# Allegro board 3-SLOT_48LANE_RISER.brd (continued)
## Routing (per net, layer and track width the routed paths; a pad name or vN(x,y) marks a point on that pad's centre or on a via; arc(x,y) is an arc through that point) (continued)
PE_SLOT2_TX_C_DN<15>: length 180.3
  BOTTOM w0.135: C78.1 218.06,44.8 218.06,45.23 218.03,45.26 217.91,45.41 217.69,45.68 217.69,45.68 212.87,46.53 212.44,46.23 212.31,45.49 212.09,45.34 211.83,45.39 211.68,45.6 211.81,46.35 211.51,46.77 211.08,47.04 127.05,61.86 v6(118.85,60.41) 96.81,56.53 90.15,51.86 89.93,51.9 89.49,51.6 89.45,51.37 89.01,51.06 88.78,51.1 88.34,50.79 88.3,50.57 87.86,50.26 87.63,50.3 87.19,49.99 87.15,49.76 86.47,49.29 83.87,48.83 79.52,49.59 78.46,50.34 77.56,50.5 71.38,50.5 69.85,52.02 64.82,52.02 61.3,55.54 61.3,55.77 60.92,56.15 60.69,56.15 60.31,56.53 60.31,56.76 59.93,57.14 59.7,57.14 59.32,57.52 59.32,57.75 58.94,58.13 58.71,58.13 57.84,59 57.84,59.73 57.99,59.88 57.99,60.42 57.84,60.57 57.84,61.11 57.99,61.26 57.99,61.8 57.84,61.95 57.84,65.79 57.94,65.89 57.94,66.65 U1.V1
PE_SLOT2_TX_C_DP<0>: length 219.2
  BOTTOM w0.135: U1.B11 71.1,74.52 71.26,74.36 73.88,74.36 74.32,74.8 78.21,74.8 78.44,74.57 82.8,74.57 125.88,82.17 v6(131.01,81.27) 132.5,81 260.82,58.26 274.09,48.96 278.32,48.21 280.94,46.38 281.23,46.05 281.62,45.5 281.62,44.82 C27.1
PE_SLOT2_TX_C_DP<1>: length 217.5
  BOTTOM w0.135: U1.B10 71.1,73.72 71.26,73.56 76.66,73.56 76.94,73.29 83.89,73.29 v6(124.51,80.45) 125.35,80.6 259.72,56.74 265.51,52.69 265.56,52.43 265.12,51.8 265.2,51.3 265.63,51 266.15,51.09 266.58,51.71 266.85,51.75 267.06,51.6 267.11,51.34 266.67,50.71 266.76,50.24 267.18,49.94 267.69,50.03 268.1,50.61 268.4,50.67 268.62,50.51 268.66,50.25 268.14,49.51 268.23,49 268.66,48.7 269.17,48.79 269.69,49.53 269.95,49.58 272.87,47.53 273.43,46.74 273.65,45.5 273.65,44.82 C28.1
PE_SLOT2_TX_C_DP<2>: length 206.7
  BOTTOM w0.135: U1.B8 71.1,72.12 71.26,71.96 73.23,71.96 73.63,72.36 76.15,72.36 76.58,71.93 84.09,71.93 125.33,79.2 127.29,78.86 v6(128.82,78.59) 190.03,67.74 254.74,56.27 260.92,51.94 261.81,51.32 261.92,51.24 262.45,50.87 269.08,46.23 269.32,45.98 269.65,45.5 269.65,44.82 C29.1
PE_SLOT2_TX_C_DP<3>: length 204.8
  BOTTOM w0.135: C30.1 265.65,44.82 265.65,45.5 265.61,45.74 265.42,46.01 263.39,47.43 263.13,47.39 262.9,47.07 262.39,46.98 261.97,47.28 261.88,47.79 262.1,48.11 262.05,48.37 261.83,48.52 261.57,48.47 261.35,48.16 261.09,48.11 260.84,48.07 260.41,48.37 260.32,48.9 260.54,49.22 260.5,49.46 254.22,53.86 251.82,55.53 126.44,77.79 v6(124.74,77.49) 123.43,77.26 85.45,70.56 75.86,70.56 75.26,71.16 73.14,71.16 73.14,71.16 71.26,71.16 71.1,71.32 U1.B7
PE_SLOT2_TX_C_DP<4>: length 196.4
  BOTTOM w0.135: U1.B5 71.1,69.72 71.26,69.56 72.51,69.56 72.91,69.96 74.37,69.96 75.16,69.16 84.51,69.16 v6(120.53,75.52) 121.86,75.75 126.43,76.56 245.98,55.35 259.28,46.03 259.56,45.64 259.56,45.63 259.65,45.5 259.65,44.82 C55.1
PE_SLOT2_TX_C_DP<5>: length 194
  BOTTOM w0.135: U1.B4 71.1,68.92 71.26,68.76 72.92,68.76 72.93,68.76 73.84,68.76 74.8,67.79 83.85,67.79 v6(123.67,74.81) 125.09,75.06 126.53,75.32 243.27,54.6 246.02,52.67 249.12,50.51 249.73,50.61 249.81,50.72 250.17,50.78 250.48,50.57 250.54,50.21 250.32,49.88 250.42,49.28 250.93,48.92 251.56,49.03 251.78,49.34 252.14,49.41 254.36,47.85 254.82,47.19 255.65,45.19 255.65,44.82 C56.1
PE_SLOT2_TX_C_DP<6>: length 187.9
  BOTTOM w0.135: U1.B2 71.1,67.32 71.26,67.16 72.6,67.16 72.98,66.78 74.09,66.78 74.48,66.4 83.17,66.4 v6(120.34,72.95) 121.76,73.2 126.26,73.99 241.28,53.71 241.52,53.54 250.76,47.07 251.58,45.91 251.58,45.9 251.65,45.5 251.65,44.82 C57.1
PE_SLOT2_TX_C_DP<7>: length 186.4
  BOTTOM w0.135: U1.B1 71.1,66.52 71.1,66.19 71.53,65.76 73.74,65.76 74.35,65.15 84.29,65.15 v6(117.27,70.97) 118.83,71.24 126.89,72.66 240.53,52.5 242.68,50.99 242.72,50.73 242.61,50.57 242.7,50.06 243.12,49.76 243.63,49.85 243.75,50.01 244.01,50.06 244.23,49.91 244.28,49.64 244.16,49.48 244.25,48.97 244.68,48.67 245.19,48.76 245.3,48.93 245.57,48.97 247.01,47.96 247.65,46.98 247.65,44.82 C58.1
PE_SLOT2_TX_C_DP<8>: length 188.5
  BOTTOM w0.135: C59.1 245.62,44.82 245.62,45.39 245.18,46.03 237.03,51.75 126.77,71.19 123.57,70.63 v6(122.1,70.37) 84.73,63.78 74.48,63.78 73.41,64.85 72.54,64.85 71.98,64.29 67.57,64.29 65.66,66.2 65.66,67.17 U1.H2
PE_SLOT2_TX_C_DP<9>: length 187.4
  BOTTOM w0.135: U1.J2 64.86,67.17 64.86,65.73 65.23,65.35 65.23,64.87 66.38,63.72 66.38,63.72 66.63,63.47 72.85,63.47 73.99,62.33 84.66,62.33 v6(117.5,68.12) 119.07,68.4 126.88,69.78 164.27,63.18 236.6,50.42 238.33,49.21 238.37,48.95 238.19,48.69 238.28,48.18 238.7,47.88 239.21,47.97 239.4,48.23 239.66,48.28 240.98,47.35 241.41,46.74 241.63,45.5 241.63,44.82 C60.1
PE_SLOT2_TX_C_DP<10>: length 185
  BOTTOM w0.135: C61.1 237.67,44.82 237.67,45.58 237.56,46.21 232.43,49.79 211.51,53.48 211.51,53.48 210.36,53.68 210.36,53.68 199.37,55.62 199.37,55.62 127.18,68.34 123.97,67.78 v6(122.17,67.46) 85.02,60.91 65.61,60.91 64.75,61.77 64.75,63.96 63.26,65.45 63.26,67.17 U1.L2
PE_SLOT2_TX_C_DP<11>: length 183.5
  BOTTOM w0.135: C62.1 233.71,44.82 233.71,45.5 233.66,45.77 232.6,47.28 230.69,48.62 229.33,48.86 229.15,48.74 228.62,48.83 228.5,49.01 227.97,49.1 227.79,48.98 227.26,49.07 227.14,49.25 222.62,50.05 221.45,50.26 211.28,52.06 211.28,52.06 200.27,54.01 200.27,54.01 199.26,54.19 199.13,54.22 126.86,67.04 119.39,65.72 v6(117.85,65.45) 80.86,58.93 65.48,58.93 63.4,61.01 63.4,63.6 62.46,64.55 62.46,67.17 U1.M2
PE_SLOT2_TX_C_DP<12>: length 181.2
  BOTTOM w0.135: C63.1 229.67,44.82 229.67,46.16 227.44,47.72 126.46,65.53 123.35,64.98 v6(121.87,64.72) 81.11,57.53 64.9,57.53 61.78,60.65 61.78,63.7 60.86,64.62 60.86,67.17 U1.P2
PE_SLOT2_TX_C_DP<13>: length 180.9
  BOTTOM w0.135: U1.R2 60.06,67.17 60.06,63.82 60.28,63.6 60.28,60.22 65.89,54.61 70.31,54.61 71.99,52.93 76.99,52.93 77.7,53.07 82.4,56.36 v6(118.1,62.65) 119.88,62.97 126.73,64.18 222.39,47.31 225.29,45.88 225.69,45.51 225.73,45.41 225.73,44.82 C64.1
PE_SLOT2_TX_C_DP<14>: length 180.3
  BOTTOM w0.135: U1.U2 58.46,67.17 58.46,65.57 58.78,65.25 58.78,62.53 58.96,62.36 58.96,59.59 65.56,52.98 70.23,52.98 71.69,51.53 79.5,51.53 81.14,50.38 83.31,50 85.61,50.38 95.51,57.3 111.25,60.08 v6(120.93,61.79) 123.14,62.18 126.99,62.86 220.26,46.41 221.27,45.69 221.76,45.21 221.76,44.85 C65.1
PE_SLOT2_TX_C_DP<15>: length 180.2
  BOTTOM w0.135: U1.V2 57.63,67.15 57.63,66.01 57.53,65.91 57.53,58.88 64.7,51.71 69.73,51.71 71.25,50.19 77.53,50.19 78.34,50.05 79.4,49.31 83.87,48.52 86.59,49 96.93,56.24 v6(117.39,59.85) 118.9,60.11 127.05,61.55 210.96,46.75 211.33,46.49 211.48,46.27 211.35,45.53 211.65,45.11 212.16,45.02 212.59,45.31 212.72,46.06 212.94,46.21 217.53,45.4 217.64,45.26 217.68,45.21 217.76,45.12 217.76,44.85 C66.1
PE_SLOT2_TX_DN<0>: length 7.4
  BOTTOM w0.135: J2.B15 280.59,38.51 arc(280.65,38.55) 280.72,38.57 281.17,38.57 arc(281.76,38.81) 282,39.4 282,43.39 C31.2
PE_SLOT2_TX_DN<1>: length 7.5
  BOTTOM w0.135: C32.2 273.98,43.34 273.98,42.44 274.16,42.26 274.16,41.82 273.98,41.65 273.98,41.21 274.16,41.03 274.16,40.59 273.98,40.41 273.98,39.34 arc(274.16,38.92) 274.58,38.74 275.01,38.74 arc(275.33,38.96) 275.25,39.33 J2.B20
PE_SLOT2_TX_DN<2>: length 7.5
  BOTTOM w0.135: J2.B24 271.25,39.33 arc(271.33,38.96) 271.01,38.74 270.58,38.74 arc(270.16,38.92) 269.98,39.34 269.98,40.41 270.16,40.59 270.16,41.03 269.98,41.21 269.98,41.65 270.16,41.82 270.16,42.26 269.98,42.44 269.98,43.34 C33.2
PE_SLOT2_TX_DN<3>: length 7.5
  BOTTOM w0.135: C34.2 265.98,43.34 265.98,42.44 266.16,42.26 266.16,41.82 265.98,41.65 265.98,41.21 266.16,41.03 266.16,40.59 265.98,40.41 265.98,39.34 arc(266.16,38.92) 266.58,38.74 267.01,38.74 arc(267.33,38.96) 267.25,39.33 J2.B28
PE_SLOT2_TX_DN<4>: length 7.5
  BOTTOM w0.135: C67.2 259.98,43.34 259.98,42.44 260.16,42.26 260.16,41.82 259.98,41.65 259.98,41.21 260.16,41.03 260.16,40.59 259.98,40.41 259.98,39.34 arc(260.16,38.92) 260.58,38.74 261.01,38.74 arc(261.33,38.96) 261.25,39.33 J2.B34
PE_SLOT2_TX_DN<5>: length 7.5
  BOTTOM w0.135: C68.2 255.98,43.34 255.98,42.44 256.16,42.26 256.16,41.82 255.98,41.65 255.98,41.21 256.16,41.03 256.16,40.59 255.98,40.41 255.98,39.34 arc(256.16,38.92) 256.58,38.74 257.01,38.74 arc(257.33,38.96) 257.25,39.33 J2.B38
PE_SLOT2_TX_DN<6>: length 7.5
  BOTTOM w0.135: C69.2 251.98,43.34 251.98,42.44 252.16,42.26 252.16,41.82 251.98,41.65 251.98,41.21 252.16,41.03 252.16,40.59 251.98,40.41 251.98,39.34 arc(252.16,38.92) 252.58,38.74 253.01,38.74 arc(253.33,38.96) 253.25,39.33 J2.B42
PE_SLOT2_TX_DN<7>: length 7.5
  BOTTOM w0.135: C70.2 247.98,43.34 247.98,42.44 248.16,42.26 248.16,41.82 247.98,41.65 247.98,41.21 248.16,41.03 248.16,40.59 247.98,40.41 247.98,39.34 arc(248.16,38.92) 248.58,38.74 249.01,38.74 arc(249.33,38.96) 249.25,39.33 J2.B46
PE_SLOT2_TX_DN<8>: length 7.4
  BOTTOM w0.135: J2.B51 244.59,38.51 arc(244.65,38.55) 244.72,38.57 245.17,38.57 arc(245.76,38.81) 246,39.4 246,43.39 C71.2
PE_SLOT2_TX_DN<9>: length 7.4
  BOTTOM w0.135: J2.B55 240.59,38.51 arc(240.65,38.55) 240.72,38.57 241.17,38.57 arc(241.76,38.81) 242,39.4 242,43.38 C72.2
PE_SLOT2_TX_DN<10>: length 7.4
  BOTTOM w0.135: J2.B59 236.59,38.51 arc(236.65,38.55) 236.72,38.57 237.17,38.57 arc(237.76,38.81) 238,39.4 238,43.34 C73.2
PE_SLOT2_TX_DN<11>: length 7.4
  BOTTOM w0.135: J2.B63 232.59,38.51 arc(232.65,38.55) 232.72,38.57 233.17,38.57 arc(233.76,38.81) 234,39.4 234,43.3 C74.2
PE_SLOT2_TX_DN<12>: length 7.4
  BOTTOM w0.135: J2.B67 228.59,38.51 arc(228.65,38.55) 228.72,38.57 229.17,38.57 arc(229.76,38.81) 230,39.4 230,43.34 C75.2
PE_SLOT2_TX_DN<13>: length 7.4
  BOTTOM w0.135: C76.2 226,43.28 226,39.4 arc(225.76,38.81) 225.17,38.57 224.72,38.57 arc(224.65,38.55) 224.59,38.51 J2.B71
PE_SLOT2_TX_DN<14>: length 7.4
  BOTTOM w0.135: C77.2 222,43.28 222,39.4 arc(221.76,38.81) 221.17,38.57 220.72,38.57 arc(220.65,38.55) 220.59,38.51 J2.B75
PE_SLOT2_TX_DN<15>: length 7.4
  BOTTOM w0.135: C78.2 218,43.28 218,39.4 arc(217.76,38.81) 217.17,38.57 216.72,38.57 arc(216.65,38.55) 216.59,38.51 J2.B79
PE_SLOT2_TX_DP<0>: length 7.4
  BOTTOM w0.135: C27.2 281.7,43.24 281.7,42.34 281.54,42.19 281.54,41.78 281.7,41.63 281.7,41.23 281.54,41.07 281.54,40.67 281.7,40.52 281.7,39.4 arc(281.54,39.03) 281.17,38.87 280.58,38.87 arc(280.34,39.03) 280.39,39.32 J2.B14
PE_SLOT2_TX_DP<1>: length 7.5
  BOTTOM w0.135: C28.2 273.68,43.29 273.68,39.34 arc(273.94,38.71) 274.58,38.44 275.15,38.44 arc(275.63,38.24) 275.83,37.76 J2.B19
PE_SLOT2_TX_DP<2>: length 7.5
  BOTTOM w0.135: C29.2 269.68,43.29 269.68,39.34 arc(269.94,38.71) 270.58,38.44 271.15,38.44 arc(271.63,38.24) 271.83,37.76 J2.B23
PE_SLOT2_TX_DP<3>: length 7.5
  BOTTOM w0.135: C30.2 265.68,43.29 265.68,39.34 arc(265.94,38.71) 266.58,38.44 267.15,38.44 arc(267.63,38.24) 267.83,37.76 J2.B27
PE_SLOT2_TX_DP<4>: length 7.5
  BOTTOM w0.135: J2.B33 261.83,37.76 arc(261.63,38.24) 261.15,38.44 260.58,38.44 arc(259.94,38.71) 259.68,39.34 259.68,43.29 C55.2
PE_SLOT2_TX_DP<5>: length 7.5
  BOTTOM w0.135: C56.2 255.68,43.29 255.68,39.34 arc(255.94,38.71) 256.58,38.44 257.15,38.44 arc(257.63,38.24) 257.83,37.76 J2.B37
PE_SLOT2_TX_DP<6>: length 7.5
  BOTTOM w0.135: C57.2 251.68,43.29 251.68,39.34 arc(251.94,38.71) 252.58,38.44 253.15,38.44 arc(253.63,38.24) 253.83,37.76 J2.B41
PE_SLOT2_TX_DP<7>: length 7.5
  BOTTOM w0.135: J2.B45 249.83,37.76 arc(249.63,38.24) 249.15,38.44 248.58,38.44 arc(247.94,38.71) 247.68,39.34 247.68,43.29 C58.2
PE_SLOT2_TX_DP<8>: length 7.4
  BOTTOM w0.135: C59.2 245.7,43.24 245.7,42.34 245.54,42.19 245.54,41.78 245.7,41.63 245.7,41.23 245.54,41.07 245.54,40.67 245.7,40.52 245.7,39.4 arc(245.54,39.03) 245.17,38.87 244.58,38.87 arc(244.34,39.03) 244.39,39.32 J2.B50
PE_SLOT2_TX_DP<9>: length 7.4
  BOTTOM w0.135: C60.2 241.7,43.25 241.7,42.34 241.54,42.19 241.54,41.78 241.7,41.63 241.7,41.23 241.54,41.07 241.54,40.67 241.7,40.52 241.7,39.4 arc(241.54,39.03) 241.17,38.87 240.56,38.87 arc(240.33,39.03) 240.38,39.31 J2.B54
PE_SLOT2_TX_DP<10>: length 7.4
  BOTTOM w0.135: J2.B58 236.36,39.28 arc(236.31,39.02) 236.53,38.87 237.17,38.87 arc(237.54,39.03) 237.69,39.4 237.69,40.52 237.54,40.67 237.54,41.07 237.69,41.23 237.69,41.63 237.54,41.78 237.54,42.19 237.69,42.34 237.69,43.29 C61.2
PE_SLOT2_TX_DP<11>: length 7.4
  BOTTOM w0.135: C62.2 233.69,43.33 233.69,42.34 233.54,42.19 233.54,41.78 233.69,41.63 233.69,41.23 233.54,41.07 233.54,40.67 233.69,40.52 233.69,39.4 arc(233.54,39.03) 233.17,38.87 232.5,38.87 arc(232.29,39.01) 232.34,39.26 J2.B62
PE_SLOT2_TX_DP<12>: length 7.4
  BOTTOM w0.135: J2.B66 228.36,39.29 arc(228.31,39.02) 228.53,38.87 229.17,38.87 arc(229.54,39.03) 229.69,39.4 229.69,40.52 229.54,40.67 229.54,41.07 229.69,41.23 229.69,41.63 229.54,41.78 229.54,42.19 229.69,42.34 229.69,43.29 C63.2
PE_SLOT2_TX_DP<13>: length 7.4
  BOTTOM w0.135: C64.2 225.7,43.35 225.7,42.34 225.54,42.19 225.54,41.78 225.7,41.63 225.7,41.23 225.54,41.07 225.54,40.67 225.7,40.52 225.7,39.4 arc(225.54,39.03) 225.17,38.87 224.5,38.87 arc(224.29,39.01) 224.34,39.26 J2.B70
PE_SLOT2_TX_DP<14>: length 7.4
  BOTTOM w0.135: J2.B74 220.34,39.26 arc(220.29,39.01) 220.5,38.87 221.17,38.87 arc(221.54,39.03) 221.7,39.4 221.7,40.52 221.54,40.67 221.54,41.07 221.7,41.23 221.7,41.63 221.54,41.78 221.54,42.19 221.7,42.34 221.7,43.35 C65.2
PE_SLOT2_TX_DP<15>: length 7.4
  BOTTOM w0.135: C66.2 217.7,43.35 217.7,42.34 217.54,42.19 217.54,41.78 217.7,41.63 217.7,41.23 217.54,41.07 217.54,40.67 217.7,40.52 217.7,39.4 arc(217.54,39.03) 217.17,38.87 216.5,38.87 arc(216.29,39.01) 216.34,39.26 J2.B78
PE_SLOT3_PRES_N: length 175.2
  TOP w0.114: J3.B81 213.22,78.39 211.2,80.42 205.46,80.42 200.97,75.92 190.4,75.92 189.31,74.83 159.3,74.83 133.23,100.89 v2(114.25,100.89) ; R45.2 59.01,97.92 64.48,103.39 105.66,103.39 v2(107.37,101.68)
  IN2 w0.147: v2(107.37,101.68) 108.15,100.89 v2(114.25,100.89)
PE_SLOT3_RX_DN<0>: length 249.2
  IN2 w0.089: 57.53,85.19 57.53,85.16 57.48,85.12 57.47,84.99 57.47,82.55 v3(57.65,82.37)
  IN2 w0.145: 57.53,85.19 57.58,85.69 57.73,85.82 57.79,86.43 57.66,86.59 57.71,87.16 57.84,87.27 57.9,87.93 57.79,88.06 57.86,88.81 58.13,89.2 58.33,89.23 58.66,89.71 58.62,89.91 58.96,90.38 59.16,90.42 59.49,90.89 59.45,91.09 59.79,91.57 59.99,91.6 60.32,92.08 60.28,92.28 60.51,92.6 63.87,94.95 64.47,95.06 64.61,94.96 65.26,95.07 65.36,95.21 65.93,95.32 66.07,95.21 66.71,95.33 66.81,95.47 68.75,95.81 73.01,98.8 73.59,98.9 73.74,98.8 74.38,98.91 74.48,99.06 75.05,99.16 75.17,99.07 75.86,99.19 75.95,99.31 83.09,100.57 86.81,99.92 86.9,99.78 87.55,99.67 87.68,99.76 88.25,99.66 88.35,99.52 88.98,99.41 89.12,99.51 89.69,99.41 89.78,99.28 90.44,99.17 90.56,99.26 91.13,99.15 91.21,99.04 91.89,98.92 92.01,99 104.53,96.79 105.39,96.94 105.51,96.86 106.16,96.98 106.25,97.09 106.82,97.2 106.93,97.11 107.59,97.23 107.67,97.35 108.24,97.45 108.36,97.36 109.02,97.48 109.1,97.6 129.58,101.21 129.7,101.12 130.39,101.24 130.48,101.37 132.66,101.76 136.67,101.05 143.25,102.21 171.41,97.24 189.42,100.42 189.52,100.34 190.23,100.47 190.31,100.57 191.05,100.71 191.15,100.63 191.86,100.76 191.93,100.86 193.18,101.08 205.8,98.86 212.11,99.97 272.89,89.25 272.89,89.25 273.67,89.12 275.82,87.75 276.15,87.27 276.13,87.15 276.53,86.58 276.65,86.56 276.98,86.08 276.96,85.94 277.34,85.39 277.49,85.37 277.72,85.03 278.07,83.07 277.67,80.85 277.67,79.94 278.7,78.92 278.7,75.32 278.55,75.16 278.42,75.1 278.19,75.17 J3.A17
  BOTTOM w0.135: U1.V20 v3(57.65,82.37)
PE_SLOT3_RX_DN<1>: length 249.3
  IN2 w0.089: 58.68,84.32 58.67,84.3 58.62,84.27 58.56,84.15 58.39,83.91 58.03,83.38 58.03,83 58.27,82.75 58.27,82.55 v3(58.45,82.37)
  IN2 w0.145: 58.68,84.32 58.73,84.45 58.85,85.12 58.77,85.59 58.87,86.15 59,86.24 59.12,86.92 59.03,87.05 59.08,87.38 59.13,87.62 59.27,87.72 59.39,88.38 59.29,88.52 59.38,89.08 59.72,89.55 59.86,89.58 60.25,90.14 60.23,90.29 61.02,91.41 62.35,92.35 62.49,92.33 63.06,92.73 63.09,92.86 64.21,93.65 65.61,93.9 65.75,93.8 66.39,93.91 66.49,94.05 67.06,94.15 67.19,94.06 67.85,94.17 67.94,94.31 68.51,94.41 68.63,94.32 69.3,94.44 69.39,94.56 69.96,94.66 70.07,94.59 70.76,94.71 70.84,94.82 71.41,94.92 71.55,94.82 72.19,94.94 72.29,95.07 75.65,95.67 76.78,95.47 77.24,95.79 77.5,97.27 77.67,97.39 78.03,97.33 78.15,97.16 77.89,95.68 78.17,95.26 78.29,95.24 78.67,95.18 79.08,95.47 79.34,96.95 79.51,97.07 79.87,97.01 79.99,96.84 79.72,95.35 80.01,94.94 83.45,94.34 87.89,95.12 87.89,95.12 97.59,96.83 104.21,95.66 132.82,100.71 133.28,100.63 133.35,100.52 134.09,100.39 134.19,100.46 134.76,100.36 134.84,100.25 135.56,100.13 135.67,100.2 136.26,100.1 143.38,101.35 171.67,96.38 193.37,100.2 205.87,98 212.25,99.13 267.55,89.38 270.36,88.88 273.05,87 273.54,86.31 273.66,85.57 273.66,85.26 273.55,85.15 273.55,84.45 273.66,84.33 273.66,83.75 273.53,83.62 273.53,82.96 273.66,82.83 273.66,82.25 273.53,82.12 273.53,81.45 273.66,81.32 273.66,79.87 272.69,78.89 272.69,75.19 272.95,74.93 273.14,74.83 273.2,74.64 J3.A22
  BOTTOM w0.135: U1.U20 v3(58.45,82.37)
PE_SLOT3_RX_DN<2>: length 235.9
  IN2 w0.089: v3(60.05,82.37) 59.87,82.55 59.87,85.48 59.91,85.53 59.91,85.55
  IN2 w0.145: 59.91,85.55 59.91,85.69 60.19,87.25 60.34,87.35 60.34,87.38 60.45,87.98 60.34,88.14 60.45,88.75 60.84,89.31 61,89.33 61.39,89.89 61.36,90.05 61.75,90.6 62.16,90.89 62.33,90.86 62.9,91.26 62.93,91.43 63.4,91.76 63.58,91.73 64.14,92.13 64.18,92.3 64.68,92.65 65.68,92.83 65.82,92.74 66.48,92.85 66.57,92.99 67.14,93.09 67.26,93.01 67.95,93.13 68.03,93.25 68.6,93.35 68.72,93.27 69.41,93.39 69.49,93.5 70.06,93.6 70.18,93.52 70.87,93.65 70.95,93.76 71.52,93.86 71.63,93.79 72.34,93.91 72.41,94.02 72.98,94.12 73.09,94.05 73.8,94.17 73.87,94.28 75.56,94.57 83.21,93.22 84.9,93.52 85.02,93.43 85.68,93.55 85.77,93.67 86.34,93.78 86.46,93.69 87.12,93.81 87.21,93.93 87.78,94.03 87.9,93.94 88.56,94.06 88.64,94.18 89.22,94.28 89.34,94.2 90,94.31 90.08,94.44 90.65,94.54 90.78,94.45 91.44,94.57 91.52,94.69 92.09,94.79 93.53,95.05 93.53,95.05 94.97,95.3 97.7,95.78 104.04,94.66 132.29,99.64 135.68,99.04 143.62,100.44 144.47,100.29 172.55,95.34 194.19,99.15 206.38,97 213,98.17 265.47,88.92 268.54,86.77 269.62,85.23 270.03,82.89 269.66,80.8 269.66,79.87 268.69,78.89 268.69,75.19 268.95,74.93 269.14,74.84 269.15,74.82 269.21,74.66 J3.A26
  BOTTOM w0.135: U1.R20 v3(60.05,82.37)
PE_SLOT3_RX_DN<3>: length 234.2
  IN2 w0.089: v3(60.85,82.37) 60.43,82.79 60.43,83.77 60.46,83.94 60.84,84.48 60.9,84.86 60.93,84.99 60.98,85.03 60.98,85.05
  IN2 w0.145: 60.98,85.05 61.07,85.52 61.19,85.61 61.3,86.26 61.22,86.39 61.32,86.96 61.45,87.05 61.51,87.38 61.57,87.68 61.47,87.82 61.59,88.49 62.65,90.01 62.97,90.23 63.16,90.2 63.66,90.55 63.7,90.74 64.86,91.56 65.83,91.73 65.96,91.64 66.61,91.75 66.7,91.88 67.27,91.98 67.4,91.89 68.05,92.01 68.14,92.14 68.71,92.24 68.84,92.15 69.5,92.26 69.58,92.39 70.16,92.49 70.28,92.4 70.94,92.52 71.03,92.65 75.64,93.46 82.98,92.16 83.69,92.04 85,92.27 85.13,92.18 85.77,92.29 85.86,92.42 86.43,92.52 86.53,92.45 87.23,92.58 87.3,92.67 87.87,92.78 87.99,92.69 88.65,92.81 88.73,92.93 89.31,93.03 89.4,92.96 90.1,93.09 90.17,93.18 91.17,93.36 94.16,92.83 94.63,92.92 94.92,93.33 94.78,94.15 94.93,94.37 95.2,94.42 95.42,94.26 95.57,93.44 95.98,93.15 96.47,93.24 96.76,93.65 96.61,94.47 96.77,94.7 97.04,94.74 97.26,94.59 97.4,93.76 97.81,93.48 101.57,94.14 103.77,93.75 104.78,93.93 106.23,94.19 106.23,94.19 107.68,94.44 107.68,94.44 108.56,94.59 108.56,94.6 131.87,98.71 135.54,98.06 143.94,99.54 144.4,99.46 172.97,94.42 194.11,98.15 206.41,95.98 213.59,97.25 260.84,88.91 261.44,88.49 261.46,88.36 262.04,87.96 262.17,87.98 262.65,87.65 262.66,87.56 263.29,87.12 263.38,87.13 264.41,86.41 265.66,84.62 265.66,83.82 265.57,83.72 265.57,82.97 265.66,82.88 265.66,82.3 265.56,82.19 265.56,81.46 265.66,81.35 265.66,79.87 264.69,78.89 264.69,75.19 264.95,74.93 265.14,74.84 265.15,74.82 265.24,74.56 264.92,73.93 J3.A30
  BOTTOM w0.135: U1.P20 v3(60.85,82.37)
PE_SLOT3_RX_DN<4>: length 222.9
  IN2 w0.145: v3(63.25,82.37) 62.99,82.11 62.79,82.11 62.57,82.32 62.57,82.82 62.64,82.89 62.64,83.68 62.57,83.75 62.57,84.33 62.66,84.42 62.66,85.17 62.57,85.26 62.57,85.84 62.67,85.94 62.67,86.67 62.57,86.77 62.57,87.29 62.6,87.46 63.53,88.78 63.89,89.04 65,89.23 65.88,89.08 66.62,89.19 68.08,90.21 68.2,90.26 71.83,90.9 71.96,90.81 72.66,90.93 72.75,91.06 73.32,91.16 73.45,91.07 74.14,91.2 74.24,91.33 74.81,91.43 74.92,91.35 75.64,91.47 75.72,91.59 76.29,91.69 76.41,91.61 77.13,91.74 77.21,91.85 77.95,91.98 83.73,90.96 91.34,92.3 94.5,91.75 95.35,91.9 95.49,91.8 96.14,91.91 96.24,92.05 96.81,92.16 96.98,92.04 97.59,92.15 97.71,92.31 98.28,92.41 98.43,92.31 99.07,92.42 99.17,92.57 101.63,93.01 103.49,92.68 131.62,97.64 134.83,97.07 144.02,98.69 144.48,98.61 172.97,93.59 194.15,97.32 206.4,95.16 213.59,96.43 257.73,88.64 258.67,87.99 259.42,86.92 259.66,85.52 259.66,79.87 258.69,78.89 258.69,75.19 258.95,74.93 259.14,74.84 259.15,74.82 259.21,74.66 J3.A36
  BOTTOM w0.124: U1.M20 v3(63.25,82.37)
PE_SLOT3_RX_DN<5>: length 222.6
  IN2 w0.089: 63.82,85.76 63.81,85.74 63.75,85.72 63.33,84.72 63.33,84.54 63.42,84.45 63.42,84.1 63.33,84.01 63.33,83.74 63.42,83.65 63.42,83.36 63.33,83.27 63.33,83.09 63.51,82.91 63.62,82.91 63.79,82.74 63.79,82.63 v3(64.05,82.37)
  IN2 w0.145: 63.82,85.76 64.15,86.23 64.46,86.45 64.6,86.42 64.98,86.69 65,86.83 65.2,86.96 65.65,87.04 65.73,86.99 66.47,87.12 66.53,87.2 67.53,87.38 68.86,88.3 69.04,88.27 69.51,88.6 69.54,88.78 69.91,89.04 70.41,89.13 70.51,89.06 71.17,89.17 71.23,89.25 71.66,89.33 72.39,89.2 72.47,89.09 73.18,88.96 73.3,89.04 73.87,88.94 73.96,88.81 74.65,88.69 74.78,88.78 76.64,88.45 77.53,88.61 77.82,89.02 77.52,90.73 77.67,90.95 77.94,91 78.16,90.85 78.46,89.13 78.88,88.85 79.37,88.93 79.66,89.35 79.44,90.56 79.56,90.73 79.92,90.79 80.09,90.67 80.3,89.46 80.71,89.17 82.54,89.49 82.63,89.43 83.43,89.57 83.49,89.66 84.07,89.76 84.17,89.69 84.95,89.83 85.02,89.93 85.59,90.03 85.7,89.95 86.47,90.09 86.55,90.2 87.12,90.3 87.23,90.22 88,90.36 88.07,90.47 88.64,90.57 88.75,90.5 89.53,90.64 89.6,90.74 92.14,91.19 94.65,90.74 95.85,90.96 95.97,90.88 96.75,91.01 96.83,91.13 97.4,91.23 97.51,91.15 98.29,91.29 98.37,91.4 98.94,91.5 99.04,91.43 99.84,91.57 99.91,91.67 101.55,91.96 103.42,91.63 131.95,96.66 134.8,96.16 144.06,97.79 144.06,97.79 144.98,97.63 172.97,92.7 194.19,96.44 206.23,94.31 213.26,95.55 223.55,93.74 233.83,91.93 233.83,91.93 254.4,88.3 255.03,87.86 255.47,87.23 255.66,86.11 255.66,79.87 254.69,78.89 254.69,75.19 254.95,74.93 255.14,74.84 255.15,74.82 255.21,74.66 J3.A40
  BOTTOM w0.135: U1.L20 v3(64.05,82.37)
PE_SLOT3_RX_DN<6>: length 209.3
  IN2 w0.089: v3(65.65,82.37) 65.48,82.54 65.48,82.61 65.35,82.74 65.35,82.84 65.07,83.12 64.96,83.12 64.81,83.27 64.81,83.79 64.89,83.86 64.89,84.36 64.81,84.44 64.81,84.74 64.86,84.78 64.86,84.8
  IN2 w0.145: 64.86,84.8 64.86,85.01 64.93,85.38 65.3,85.91 65.83,86.29 67.7,86.62 67.81,86.54 68.49,86.66 68.56,86.77 69.13,86.87 69.24,86.79 69.91,86.91 69.99,87.02 71.52,87.29 73.46,86.95 74.13,87.06 74.24,86.98 74.94,87.1 75.04,87.25 75.56,87.35 75.72,87.23 76.4,87.35 76.51,87.51 77.03,87.6 77.22,87.47 77.84,87.58 77.98,87.77 78.49,87.86 78.67,87.74 79.33,87.86 79.45,88.03 91.84,90.22 94.68,89.72 95.83,89.92 95.94,89.85 96.66,89.97 96.73,90.08 97.3,90.18 97.43,90.09 98.11,90.21 98.2,90.34 98.77,90.44 98.9,90.35 99.58,90.47 99.67,90.59 101.58,90.93 103.66,90.57 104.51,90.72 104.65,90.62 105.35,90.74 105.45,90.88 106.02,90.98 106.16,90.89 106.86,91.01 106.96,91.15 131.82,95.53 134.49,95.06 135.25,95.2 135.37,95.11 136.06,95.23 136.14,95.35 136.71,95.45 136.83,95.37 137.53,95.49 137.61,95.61 144.54,96.83 172.91,91.83 194.28,95.6 194.36,95.58 206.22,93.49 213.26,94.74 249.67,88.32 250.93,87.44 251.42,86.73 251.66,85.34 251.66,79.87 250.69,78.89 250.69,75.19 250.95,74.93 251.14,74.84 251.15,74.82 251.21,74.66 J3.A44
  BOTTOM w0.135: U1.J20 v3(65.65,82.37)
PE_SLOT3_RX_DN<7>: length 209.2
  IN2 w0.089: v3(66.45,82.37) 66.27,82.55 66.27,82.97 66.34,83.03 66.34,83.57 66.27,83.63 66.27,83.95 66.28,84.08 66.33,84.12 66.33,84.14
  IN2 w0.145: J3.A48 247.21,74.66 247.15,74.82 247.14,74.84 246.95,74.93 246.69,75.19 246.69,78.96 247.68,79.95 247.68,80.75 246.78,85.85 245.5,87.68 244.44,88.42 213.26,93.92 206.22,92.68 194.38,94.76 172.48,90.9 145.55,95.65 144.54,95.83 133.91,93.95 131.54,94.37 103.91,89.5 101.87,89.86 94.89,88.63 92,89.14 91.32,89.02 91.16,88.8 91.45,87.17 91.2,86.82 90.62,86.71 90.26,86.96 89.97,88.59 89.75,88.74 89.48,88.69 89.33,88.47 89.61,86.88 89.36,86.52 88.77,86.42 88.42,86.67 88.33,87.17 88.21,87.25 88.14,87.67 88.22,87.78 88.13,88.26 87.92,88.41 87.52,88.34 87.45,88.24 86.93,88.15 86.83,88.22 86.3,88.13 86.21,88 85.63,87.9 85.5,87.99 85.01,87.9 84.93,87.78 84.34,87.67 84.22,87.76 83.73,87.67 83.64,87.55 83.05,87.44 82.93,87.53 82.44,87.44 82.36,87.32 81.77,87.22 81.64,87.3 81.16,87.22 81.07,87.09 80.48,86.99 80.36,87.08 79.87,86.99 79.78,86.87 79.2,86.76 79.07,86.85 78.48,86.75 78.42,86.66 77.65,86.52 77.56,86.58 76.97,86.48 76.91,86.39 76.15,86.25 76.05,86.32 75.42,86.21 75.34,86.09 74.38,85.92 74.26,86 73.67,85.9 73.5,85.87 73.49,85.87 72.6,86.02 72.46,85.92 71.86,86.03 71.76,86.17 70.9,86.32 69.94,86.16 69.82,85.98 69.33,85.89 69.15,86.02 68.66,85.93 68.54,85.76 68.04,85.67 67.87,85.79 67.43,85.71 66.75,85.24 66.38,84.71 66.33,84.14
  BOTTOM w0.135: U1.H20 v3(66.45,82.37)
PE_SLOT3_RX_DN<8>: length 190.8
  IN2 w0.145: v3(69.65,84.77) 69.65,84.98 69.8,85.13 72.5,85.13 73.72,84.91 74.37,85.03 74.45,84.97 74.5,84.93 75,85.02 75.09,85.15 75.51,85.23 75.64,85.14 76.14,85.22 76.23,85.36 76.65,85.43 76.78,85.34 77.28,85.42 77.38,85.56 77.79,85.63 77.92,85.54 78.42,85.63 78.52,85.76 78.93,85.83 79.07,85.74 79.56,85.83 79.66,85.96 80.07,86.03 80.21,85.94 80.71,86.03 80.8,86.16 81.22,86.23 81.36,86.13 81.84,86.21 81.94,86.36 82.67,86.49 88.76,85.41 92.14,86.01 93.27,86.8 94.33,86.98 94.46,86.89 95.09,87 95.19,87.14 95.76,87.24 95.89,87.14 96.52,87.26 96.62,87.39 97.19,87.49 97.32,87.4 97.96,87.51 98.05,87.64 98.62,87.74 98.75,87.65 99.39,87.76 99.48,87.89 100.05,87.99 100.18,87.9 100.82,88.01 100.91,88.15 101.48,88.25 101.61,88.15 102.25,88.27 102.34,88.4 131.56,93.55 134.25,93.07 144.66,94.91 145.28,94.8 145.28,94.8 172.66,89.98 194.77,93.88 206.22,91.86 213.26,93.1 232.6,89.69 232.73,89.49 233.18,89.42 233.37,89.55 233.81,89.47 233.95,89.28 234.4,89.2 234.59,89.34 236.04,89.08 236.46,88.47 240.17,87.82 241.7,85.64 241.7,79.88 242.67,78.9 242.67,75.29 242.54,75.16 242.4,75.08 242.2,75.15 J3.A53
  BOTTOM w0.135: U1.D23 v3(69.65,84.77)
PE_SLOT3_RX_DN<9>: length 189.3
  IN2 w0.089: 72.89,84.31 72.87,84.31 72.82,84.35 72.29,84.35 72.2,84.26 71.84,84.26 71.75,84.35 71.4,84.35 71.31,84.26 70.95,84.26 70.86,84.35 70.04,84.35 v3(69.65,83.97)
  IN2 w0.145: 72.89,84.31 73.04,84.31 74.45,84.06 74.46,84.06 74.6,84.06 74.6,84.06 74.63,84.06 75.48,84.21 75.64,84.1 76.31,84.22 76.42,84.38 76.93,84.47 77.05,84.39 77.79,84.52 77.87,84.63 78.38,84.72 78.47,84.66 79.26,84.8 79.32,84.89 79.83,84.98 79.94,84.9 80.7,85.04 80.77,85.14 81.29,85.24 81.38,85.17 82.16,85.3 82.23,85.4 83.1,85.55 88.85,84.54 92.88,85.25 93.76,85.87 96.56,86.36 96.79,86.21 97.05,84.74 97.46,84.45 97.95,84.54 98.24,84.95 97.98,86.42 98.13,86.64 99.54,86.89 99.69,86.79 100.33,86.9 100.43,87.05 101,87.15 101.14,87.04 101.79,87.16 101.89,87.3 102.46,87.4 102.58,87.32 103.26,87.44 103.34,87.56 103.91,87.66 104.04,87.57 104.71,87.69 104.8,87.82 105.37,87.92 105.5,87.83 106.17,87.95 106.26,88.07 107.51,88.29 107.64,88.2 108.3,88.32 108.39,88.45 108.96,88.55 109.09,88.46 109.74,88.57 109.83,88.7 131.59,92.54 133.85,92.14 144.69,94.05 145.54,93.9 172.65,89.12 194.87,93.04 206.22,91.04 212.7,92.18 227.71,89.53 227.84,89.34 228.29,89.26 228.48,89.4 228.93,89.32 229.06,89.13 229.5,89.05 229.7,89.18 230.26,89.08 231.32,88.34 232.04,87.84 235.93,87.16 236.69,86.63 237.22,85.86 237.69,83.19 237.69,79.89 238.69,78.9 238.69,75.3 238.54,75.16 238.4,75.08 238.2,75.15 J3.A57
  BOTTOM w0.135: U1.D22 v3(69.65,83.97)
PE_SLOT3_RX_DN<10>: length 182.3
  IN2 w0.089: 72.25,83.35 72.23,83.34 72.18,83.38 72.05,83.36 71.57,83.27 70.99,82.87 70.35,82.75 70.04,82.75 v3(69.65,82.37)
  IN2 w0.145: 72.25,83.35 73.06,83.49 74.45,83.24 75.41,83.07 75.99,83.18 76.13,83.08 76.81,83.2 76.9,83.34 77.47,83.44 77.59,83.35 78.3,83.48 78.38,83.6 78.95,83.7 79.08,83.61 79.77,83.73 79.86,83.86 80.43,83.96 80.56,83.87 81.25,84 81.34,84.12 81.91,84.22 82.04,84.13 82.73,84.26 82.82,84.38 83.28,84.46 83.29,84.46 83.75,84.54 88.71,83.67 89.32,83.78 89.43,83.7 90.11,83.83 90.19,83.93 90.76,84.03 90.87,83.95 91.54,84.06 91.62,84.18 92.79,84.39 93.71,84.23 93.79,84.11 94.57,83.97 94.69,84.06 97.29,83.6 99.17,83.93 102.82,86.49 104.33,86.75 104.5,86.64 105.19,86.76 105.31,86.92 105.88,87.03 106,86.94 106.76,87.07 106.85,87.2 107.42,87.3 107.55,87.21 108.3,87.34 108.39,87.47 131.66,91.57 133.68,91.22 144.89,93.19 145.88,93.02 145.94,92.92 146.66,92.8 146.75,92.87 147.32,92.77 147.4,92.66 148.1,92.54 148.2,92.61 148.77,92.51 148.84,92.41 149.55,92.28 149.65,92.36 172.64,88.3 194.59,92.17 206.13,90.14 212.42,91.25 222.16,89.53 222.24,89.41 222.9,89.29 223.02,89.38 223.59,89.28 223.66,89.18 224.35,89.06 224.45,89.13 225.02,89.03 225.1,88.92 225.77,88.8 225.88,88.87 227.02,88.67 228.84,87.4 232.12,86.82 232.97,86.23 233.17,85.94 233.44,84.41 233.37,83.98 233.73,81.92 233.73,79.89 234.69,78.94 234.69,75.3 234.54,75.16 234.4,75.08 234.2,75.15 J3.A61
  BOTTOM w0.135: U1.D20 v3(69.65,82.37)
PE_SLOT3_RX_DN<11>: length 181.7
  IN2 w0.089: v3(69.65,81.57) 70.04,81.95 70.82,81.95 70.86,81.91 70.9,81.86 71.26,81.86 71.3,81.91 71.35,81.95 71.7,81.95 71.75,81.91 71.79,81.86 72.15,81.86 72.19,81.91 72.24,81.95 73.26,81.95 73.28,81.93
  IN2 w0.145: J3.A65 230.2,75.15 230.4,75.08 230.54,75.16 230.68,75.3 230.68,78.88 229.69,79.88 229.69,81.19 230.02,81.53 231.79,81.53 231.93,81.67 231.93,82.04 231.79,82.18 230.02,82.18 229.67,82.54 229.67,84.77 228.7,86.15 226.84,87.45 225.18,87.74 225.05,87.65 224.3,87.78 224.21,87.91 223.64,88.01 223.5,87.91 222.77,88.04 222.67,88.18 222.1,88.28 221.94,88.17 221.24,88.3 221.13,88.45 220.56,88.55 220.41,88.45 219.7,88.57 219.59,88.73 219.02,88.83 218.84,88.7 218.18,88.81 218.05,89 211.63,90.13 206.35,89.2 202.14,89.94 201.98,89.82 201.35,89.93 201.24,90.1 200.67,90.2 200.52,90.1 199.86,90.21 199.76,90.36 199.19,90.46 199.07,90.38 198.37,90.5 198.28,90.62 197.71,90.72 197.57,90.62 196.9,90.74 196.8,90.88 195.12,91.18 172.11,87.12 144.83,91.93 133.57,89.95 131.5,90.31 108.19,86.2 108.1,86.07 107.39,85.94 107.26,86.04 106.73,85.94 106.64,85.81 105.94,85.68 105.8,85.78 105.28,85.69 105.19,85.56 104.47,85.43 104.34,85.52 103.1,85.3 100.14,83.23 96.91,82.67 92.82,83.39 92.61,83.34 88.03,82.51 83.56,83.3 83.01,83.2 82.9,83.04 82.18,82.92 82.02,83.03 81.5,82.94 81.38,82.76 80.69,82.64 80.52,82.76 75.62,81.9 74.52,82.09 74.51,82.09 74.24,82.09 73.29,81.93 73.28,81.93
  BOTTOM w0.135: U1.D19 v3(69.65,81.57)
PE_SLOT3_RX_DN<12>: length 173.6
  IN2 w0.089: 74.45,80.49 74.43,80.49 74.38,80.53 73.41,80.53 72.89,80.9 72.26,80.9 71.34,80.26 70.87,80.17 69.86,80.17 v3(69.65,79.97)
  IN2 w0.145: J3.A69 226.2,75.15 226.4,75.08 226.54,75.16 226.68,75.3 226.68,78.88 225.68,79.88 225.68,81.07 225.96,82.63 225.49,85.25 224.75,86.31 224.75,86.31 224.01,86.83 221.34,87.3 221.2,87.2 220.56,87.31 220.47,87.45 219.9,87.55 219.75,87.45 219.13,87.56 219.03,87.7 218.46,87.81 218.33,87.71 217.68,87.83 217.59,87.96 217.02,88.06 216.87,87.96 216.25,88.07 216.15,88.21 215.58,88.31 215.44,88.22 214.8,88.33 214.71,88.47 211.17,89.09 205.94,88.17 204.56,88.41 204.45,88.33 203.72,88.46 203.64,88.57 203.07,88.67 202.95,88.59 202.23,88.72 202.15,88.84 201.58,88.94 201.45,88.85 200.75,88.97 200.65,89.1 200.08,89.2 199.97,89.12 199.24,89.25 199.16,89.36 198.59,89.46 198.48,89.38 197.75,89.51 197.67,89.63 197.1,89.73 196.95,89.62 196.28,89.74 196.18,89.89 194.43,90.2 171.67,86.18 144.65,90.95 103.14,83.63 101.04,82.16 97.09,81.46 92.57,82.26 91.05,81.99 90.95,81.84 90.28,81.72 90.13,81.83 89.55,81.73 89.47,81.6 88.75,81.47 88.63,81.56 88.01,81.46 84.41,82.09 80.45,81.39 80.37,81.29 79.69,81.16 79.58,81.24 79.01,81.14 78.92,81.02 78.26,80.9 78.14,80.99 77.56,80.88 77.47,80.75 76.83,80.63 76.69,80.73 75.3,80.49 74.45,80.49
  BOTTOM w0.135: U1.D17 v3(69.65,79.97)
PE_SLOT3_RX_DN<13>: length 173.7
  IN2 w0.089: 73.02,79.51 72.99,79.51 72.95,79.55 70.04,79.55 v3(69.65,79.17)
  IN2 w0.145: 73.02,79.51 74.19,79.51 75.39,79.3 76.35,79.47 76.47,79.38 77.14,79.5 77.22,79.62 77.79,79.72 77.91,79.64 78.59,79.76 78.67,79.88 79.24,79.98 79.34,79.91 80.05,80.03 80.12,80.13 80.69,80.23 80.82,80.14 81.47,80.25 81.57,80.39 84.79,80.95 88.08,80.37 88.79,80.5 88.93,80.4 89.63,80.52 89.73,80.66 90.3,80.76 90.44,80.66 91.13,80.79 91.23,80.93 92.82,81.21 97.02,80.47 101.22,81.21 103.4,82.73 107.02,83.37 107.24,83.22 107.35,82.59 107.71,82.34 108.29,82.44 108.54,82.8 108.43,83.43 108.59,83.65 108.85,83.7 109.07,83.54 109.17,82.98 109.53,82.73 110.12,82.83 110.37,83.19 110.27,83.75 110.42,83.97 110.69,84.02 110.91,83.87 111.01,83.3 111.37,83.05 111.95,83.15 112.2,83.51 112.1,84.08 112.26,84.3 144.76,90.03 172.02,85.22 194.13,89.12 195.97,88.8 196.04,88.69 196.58,88.6 196.68,88.67 197.11,88.6 197.18,88.49 197.72,88.4 197.82,88.47 198.25,88.4 198.34,88.27 198.83,88.18 198.96,88.27 199.39,88.2 199.47,88.08 199.99,87.99 200.11,88.07 205.36,87.14 210.52,88.05 211.58,87.87 211.69,87.71 212.27,87.61 212.42,87.72 212.86,87.64 212.97,87.5 213.56,87.39 213.71,87.49 214.15,87.41 214.27,87.24 214.81,87.14 214.98,87.26 214.99,87.27 215.44,87.19 215.55,87.02 216.11,86.92 216.27,87.03 216.28,87.04 216.72,86.96 216.85,86.78 217.38,86.68 217.55,86.8 217.56,86.81 218.01,86.73 218.12,86.58 218.69,86.48 218.84,86.58 218.85,86.58 220.06,86.37 220.83,85.83 221.16,85.36 221.69,82.37 221.69,79.87 222.68,78.88 222.68,75.3 222.54,75.16 222.4,75.08 222.2,75.15 J3.A73
  BOTTOM w0.135: U1.D16 v3(69.65,79.17)
PE_SLOT3_RX_DN<14>: length 161.4
  IN2 w0.089: 72.9,78.45 72.89,78.45 72.88,78.47 72.85,78.51 72.36,78.59 71.76,78.45 70.92,77.85 70.48,77.77 69.86,77.77 v3(69.65,77.57)
  IN2 w0.145: 72.9,78.45 74.45,78.29 75.32,78.2 76.31,78.38 76.47,78.27 76.99,78.36 77.09,78.51 77.45,78.58 77.58,78.49 78.15,78.59 78.23,78.71 78.6,78.78 78.73,78.68 79.28,78.78 79.37,78.91 79.74,78.98 79.9,78.87 80.4,78.95 80.52,79.12 80.88,79.18 81.02,79.08 81.56,79.18 81.66,79.32 82.02,79.38 82.13,79.3 82.72,79.41 82.8,79.52 84.52,79.82 88.03,79.2 92.3,79.96 96.94,79.14 148.87,88.3 172.36,84.15 175.13,84.64 175.24,84.57 175.8,84.67 175.87,84.77 176.27,84.84 176.34,84.79 176.96,84.9 177.02,84.98 177.41,85.05 177.49,84.99 178.1,85.1 178.16,85.18 193.96,87.96 200.54,86.8 200.63,86.69 201.16,86.59 201.28,86.67 201.69,86.6 201.78,86.46 202.28,86.37 202.42,86.47 202.83,86.4 202.94,86.24 203.4,86.16 203.56,86.27 203.97,86.2 204.07,86.05 204.55,85.96 204.7,86.07 205.11,86 205.21,85.85 205.7,85.77 205.84,85.87 206.25,85.8 206.35,85.66 206.85,85.57 206.98,85.67 207.39,85.6 207.5,85.44 207.97,85.36 208.13,85.47 212.8,84.64 214.91,83.17 216,82.72 217.18,81.89 217.56,81.34 217.71,80.51 217.71,79.86 218.68,78.88 218.68,75.3 218.54,75.16 218.4,75.08 218.2,75.15 J3.A77
  BOTTOM w0.135: U1.D14 v3(69.65,77.57)
PE_SLOT3_RX_DN<15>: length 160.6
  IN2 w0.089: v3(69.65,76.77) 70.04,77.15 71.12,77.15 71.16,77.1 71.21,77.06 71.61,77.06 71.65,77.1 71.7,77.15 72.1,77.15 72.15,77.1 72.19,77.06 72.59,77.06 72.64,77.1 72.68,77.15 73.4,77.15 73.44,77.11 73.46,77.11
  IN2 w0.145: J3.A81 214.2,75.15 214.4,75.08 214.54,75.16 214.68,75.3 214.68,78.88 213.67,79.89 213.67,81.36 213.54,82.06 212.79,83.13 211.98,83.7 208.63,84.29 208.54,84.23 207.97,84.33 207.91,84.42 207.49,84.49 207.38,84.41 206.84,84.51 206.76,84.62 206.35,84.69 206.25,84.62 205.7,84.72 205.62,84.82 205.21,84.89 205.1,84.82 204.56,84.91 204.48,85.02 204.07,85.1 203.95,85.01 203.42,85.11 203.34,85.22 202.93,85.3 202.81,85.22 202.28,85.31 202.2,85.42 201.79,85.5 201.65,85.4 201.16,85.48 201.06,85.63 194.73,86.74 175.23,83.3 175.23,83.3 172.27,82.78 148.69,86.94 104.16,79.09 104.01,78.87 104.1,78.35 103.85,77.99 103.26,77.89 102.9,78.14 102.81,78.66 102.59,78.81 102.32,78.77 102.17,78.54 102.27,78 102.02,77.64 101.43,77.54 101.07,77.79 100.97,78.33 100.46,78.7 99.15,78.46 99.07,78.35 98.4,78.23 98.28,78.31 97.71,78.21 97.63,78.09 96.97,77.98 96.85,78.06 96.22,77.95 92.1,78.67 91.19,78.51 91.11,78.39 90.43,78.27 90.31,78.36 89.74,78.26 89.65,78.12 88.99,78.01 88.86,78.1 87.89,77.93 84.38,78.55 82.07,78.14 81.99,78.03 81.46,77.93 81.35,78.01 80.93,77.94 80.85,77.83 80.31,77.74 80.21,77.81 79.79,77.74 79.7,77.62 79.18,77.53 79.07,77.61 78.65,77.54 78.56,77.42 78.05,77.33 77.93,77.41 77.5,77.34 77.42,77.22 76.91,77.13 76.79,77.21 75.5,76.98 73.91,77.11 73.91,77.11 73.46,77.11
  BOTTOM w0.135: U1.D13 v3(69.65,76.77)
PE_SLOT3_RX_DP<0>: length 249.3
  IN2 w0.089: v3(57.65,81.57) 57.28,81.94 57.28,85.01 57.29,85.14 57.25,85.19 57.25,85.21
  IN2 w0.145: 57.25,85.21 57.39,86.7 57.54,88.46 57.55,88.46 57.59,88.91 60.31,92.8 63.76,95.22 68.64,96.08 72.9,99.06 83.09,100.86 104.53,97.08 132.66,102.04 136.67,101.33 143.25,102.49 171.41,97.53 193.18,101.37 205.8,99.14 212.11,100.25 272.94,89.53 272.94,89.53 273.77,89.38 276.02,87.95 277.98,85.14 278.35,83.07 277.95,80.82 277.95,80.06 278.98,79.03 278.98,75.2 278.71,74.93 278.52,74.84 278.46,74.64 J3.A16
  BOTTOM w0.135: v3(57.65,81.57) 58.05,81.17 U1.V19
PE_SLOT3_RX_DP<1>: length 249.4
  IN2 w0.089: v3(58.45,81.57) 58.08,81.94 58.08,82.68 57.84,82.92 57.84,83.44 58.24,84.02 58.38,84.22 58.44,84.35 58.41,84.4 58.42,84.42
  IN2 w0.145: 58.42,84.42 58.46,84.53 58.57,85.12 58.48,85.59 58.8,87.38 59.12,89.19 60.82,91.62 64.1,93.91 75.65,95.95 76.72,95.76 76.99,95.95 77.25,97.44 77.61,97.69 78.19,97.58 78.44,97.22 78.18,95.74 78.34,95.52 78.6,95.47 78.82,95.63 79.09,97.11 79.44,97.36 80.03,97.26 80.28,96.9 80.02,95.42 80.17,95.2 83.44,94.62 87.84,95.4 97.58,97.11 104.21,95.95 132.82,100.99 136.26,100.38 139.77,101 143.38,101.64 171.67,96.66 193.37,100.49 205.87,98.28 212.25,99.41 270.47,89.15 273.25,87.2 273.8,86.42 273.94,85.6 273.94,79.76 272.97,78.78 272.97,75.31 273.12,75.16 273.26,75.08 273.46,75.15 J3.A21
  BOTTOM w0.124: U1.U19 v3(58.45,81.57)
PE_SLOT3_RX_DP<2>: length 236
  IN2 w0.089: v3(60.05,81.57) 59.68,81.94 59.68,85.48 59.63,85.53 59.63,85.55
  IN2 w0.145: 59.63,85.55 59.63,85.72 60.19,88.86 61.55,90.81 64.57,92.92 75.55,94.86 83.2,93.51 97.69,96.06 104.04,94.94 132.29,99.93 135.68,99.33 143.62,100.73 144.47,100.58 172.55,95.62 194.19,99.44 206.38,97.29 213,98.45 265.58,89.18 268.74,86.97 269.89,85.34 270.32,82.89 269.94,80.77 269.94,79.76 268.97,78.78 268.97,75.31 269.12,75.16 269.26,75.08 269.46,75.15 J3.A25
  BOTTOM w0.135: v3(60.05,81.57) 60.45,81.17 U1.R19
PE_SLOT3_RX_DP<3>: length 234.3
  IN2 w0.089: v3(60.85,81.57) 60.48,81.94 60.48,82.47 60.24,82.71 60.24,83.79 60.28,84.02 60.66,84.56 60.72,84.89 60.74,85.03 60.7,85.08 60.71,85.1
  IN2 w0.145: 60.71,85.1 61.33,88.6 62.45,90.21 64.76,91.82 75.63,93.74 83.68,92.32 91.17,93.64 94.16,93.12 94.47,93.17 94.63,93.39 94.48,94.22 94.77,94.63 95.26,94.71 95.68,94.43 95.82,93.6 96.04,93.45 96.31,93.5 96.46,93.72 96.32,94.54 96.61,94.95 97.1,95.04 97.51,94.75 97.66,93.93 97.88,93.77 101.57,94.42 103.77,94.04 104.73,94.21 104.73,94.21 108.51,94.87 108.51,94.87 131.86,98.99 135.54,98.34 143.94,99.82 144.4,99.74 172.97,94.7 194.11,98.43 206.41,96.26 213.59,97.53 260.95,89.18 264.61,86.61 265.94,84.71 265.94,79.76 264.97,78.78 264.97,75.31 265.12,75.16 265.26,75.08 265.46,75.15 J3.A29
  BOTTOM w0.135: U1.P19 61.25,81.17 v3(60.85,81.57)
PE_SLOT3_RX_DP<4>: length 223
  IN2 w0.145: J3.A35 259.46,75.15 259.26,75.08 259.12,75.16 258.97,75.31 258.97,78.78 259.94,79.76 259.94,85.54 259.68,87.03 258.87,88.19 257.84,88.91 213.59,96.71 206.4,95.45 194.15,97.61 172.97,93.87 144.48,98.9 144.02,98.98 134.83,97.36 131.62,97.92 103.49,92.96 101.63,93.29 94.5,92.03 91.34,92.59 83.73,91.25 77.95,92.27 68.1,90.53 67.97,90.48 66.55,89.48 65.88,89.36 65,89.52 63.78,89.3 63.33,88.99 62.33,87.57 62.3,87.38 62.29,87.31 62.29,82.21 62.67,81.83 62.99,81.83 v3(63.25,81.57)
  BOTTOM w0.124: U1.M19 v3(63.25,81.57)
PE_SLOT3_RX_DP<5>: length 222.7
  IN2 w0.089: v3(64.05,81.57) 63.68,81.94 63.68,82.47 63.14,83.01 63.14,84.75 63.57,85.79 63.54,85.85 63.56,85.87
  IN2 w0.145: 63.56,85.87 63.95,86.43 65.09,87.23 65.92,87.38 66.11,87.41 66.29,87.44 67.37,87.6 69.8,89.3 71.61,89.62 76.64,88.74 77.37,88.87 77.53,89.09 77.22,90.8 77.51,91.21 78.01,91.3 78.42,91.01 78.72,89.3 78.94,89.14 79.21,89.19 79.36,89.41 79.15,90.63 79.4,90.98 79.99,91.09 80.34,90.84 80.56,89.62 80.78,89.47 92.14,91.47 94.65,91.03 101.54,92.24 103.42,91.91 131.95,96.95 134.8,96.44 144.01,98.07 144.02,98.07 144.06,98.08 144.98,97.92 172.97,92.98 194.19,96.72 206.23,94.6 213.26,95.84 254.51,88.57 255.23,88.06 255.73,87.34 255.94,86.13 255.94,79.76 254.97,78.78 254.97,75.31 255.12,75.16 255.26,75.08 255.46,75.15 J3.A39
  BOTTOM w0.135: U1.L19 v3(64.05,81.57)
PE_SLOT3_RX_DP<6>: length 209.4
  IN2 w0.089: v3(65.65,81.57) 65.28,81.94 65.28,82.54 64.62,83.19 64.62,84.74 64.58,84.78 64.58,84.8
  IN2 w0.145: 64.58,84.8 64.58,85.03 64.66,85.49 65.1,86.11 65.72,86.55 69.94,87.3 69.94,87.3 70.39,87.38 71.52,87.57 72.62,87.38 73.37,87.24 74.12,87.38 85.59,89.4 91.84,90.5 94.68,90 101.58,91.22 103.66,90.85 131.82,95.82 134.49,95.35 144.54,97.12 145.51,96.95 172.91,92.12 194.28,95.88 194.36,95.87 206.22,93.78 213.26,95.02 249.78,88.58 251.13,87.64 251.69,86.84 251.94,85.37 251.94,79.76 250.97,78.78 250.97,75.31 251.12,75.16 251.26,75.08 251.46,75.15 J3.A43
  BOTTOM w0.135: U1.J19 v3(65.65,81.57)
PE_SLOT3_RX_DP<7>: length 209.3
  IN2 w0.089: v3(66.45,81.57) 66.45,81.84 66.08,82.21 66.08,83.96 66.09,84.1 66.05,84.14 66.05,84.17
  IN2 w0.145: 66.05,84.17 66.05,84.17 66.11,84.81 66.55,85.44 67.32,85.98 70.9,86.61 73.49,86.15 74.45,86.32 87.99,88.71 88.39,88.42 88.67,86.83 88.84,86.71 89.2,86.78 89.31,86.94 89.03,88.54 89.32,88.95 89.82,89.04 90.23,88.75 90.51,87.13 90.68,87.01 91.04,87.07 91.16,87.24 90.87,88.86 91.16,89.27 92,89.42 94.89,88.91 101.87,90.14 103.91,89.78 131.54,94.65 133.91,94.24 144.54,96.11 145.55,95.93 172.48,91.18 194.38,95.05 206.22,92.96 213.26,94.2 244.55,88.68 245.7,87.88 247.04,85.96 247.96,80.77 247.96,79.83 246.97,78.84 246.97,75.31 247.12,75.16 247.26,75.08 247.46,75.15 J3.A47
  BOTTOM w0.135: U1.H19 v3(66.45,81.57)
PE_SLOT3_RX_DP<8>: length 190.9
  IN2 w0.145: J3.A52 242.46,74.64 242.52,74.84 242.7,74.93 242.95,75.18 242.95,79.02 241.98,79.99 241.98,85.72 240.33,88.08 236.63,88.73 236.2,89.34 234.64,89.61 213.26,93.38 206.22,92.14 194.77,94.16 172.66,90.26 145.36,95.07 145.33,95.08 145.3,95.08 144.66,95.2 134.25,93.36 131.56,93.83 102.29,88.67 93.16,87.06 92.03,86.27 88.76,85.7 82.66,86.77 74.45,85.32 73.72,85.2 72.52,85.41 69.68,85.41 69.04,84.77 v3(68.85,84.77)
  BOTTOM w0.135: U1.E23 v3(68.85,84.77)
PE_SLOT3_RX_DP<9>: length 189.4
  IN2 w0.089: 72.89,84.59 72.87,84.59 72.82,84.54 69.96,84.54 69.78,84.37 69.42,84.37 v3(68.85,83.97)
  IN2 w0.145: J3.A56 238.45,74.65 238.51,74.83 238.52,74.84 238.7,74.93 238.96,75.19 238.96,79.02 237.97,80.01 237.97,83.22 237.49,85.97 236.89,86.83 236.04,87.42 232.15,88.11 231.05,88.87 230.37,89.35 229.75,89.46 212.7,92.47 206.22,91.32 194.87,93.32 172.65,89.41 145.54,94.19 144.69,94.34 133.85,92.42 131.59,92.82 97.97,86.9 97.68,86.49 97.94,85.01 97.79,84.79 97.52,84.74 97.3,84.9 97.04,86.37 96.63,86.66 93.65,86.13 92.77,85.52 88.85,84.82 83.1,85.84 83.09,85.84 74.6,84.34 74.6,84.34 74.46,84.34 74.45,84.34 73.06,84.59 72.89,84.59
  BOTTOM w0.135: U1.E22 v3(68.85,83.97)
PE_SLOT3_RX_DP<10>: length 182.4
  IN2 w0.089: 72.21,83.62 72.18,83.62 72.15,83.57 72.02,83.54 71.49,83.45 70.92,83.05 70.33,82.94 69.96,82.94 69.78,82.77 69.42,82.77 v3(68.85,82.37)
  IN2 w0.145: J3.A60 234.49,74.58 234.58,74.87 234.7,74.93 234.96,75.19 234.96,79.06 234.01,80.01 234.01,81.95 233.65,83.98 233.73,84.41 233.44,86.05 233.17,86.43 232.23,87.09 228.95,87.67 227.13,88.94 212.42,91.53 206.13,90.42 194.59,92.46 172.64,88.59 144.89,93.48 133.68,91.5 131.66,91.86 102.71,86.75 99.06,84.19 97.29,83.88 92.79,84.67 88.71,83.95 83.75,84.83 83.15,84.72 82.77,84.66 75.41,83.36 74.45,83.53 73.06,83.77 72.21,83.62
  BOTTOM w0.135: U1.E20 v3(68.85,82.37)
PE_SLOT3_RX_DP<11>: length 181.7
  IN2 w0.089: v3(68.85,81.57) 69.42,81.97 69.78,81.97 69.96,82.14 73.19,82.14 73.19,82.15 73.21,82.15 73.27,82.21
  IN2 w0.145: J3.A64 230.45,74.65 230.51,74.83 230.7,74.93 230.96,75.19 230.96,78.99 229.97,79.99 229.97,81.08 230.14,81.25 231.9,81.25 232.21,81.56 232.21,82.15 231.9,82.46 230.14,82.46 229.95,82.65 229.95,84.85 228.9,86.35 226.95,87.71 211.63,90.41 206.35,89.48 195.12,91.46 172.11,87.41 144.83,92.21 133.57,90.23 131.5,90.59 102.99,85.57 100.03,83.5 96.91,82.95 92.82,83.67 92.56,83.62 88.03,82.8 83.56,83.59 75.62,82.18 74.45,82.39 74.38,82.4 73.27,82.21
  BOTTOM w0.135: U1.E19 v3(68.85,81.57)
PE_SLOT3_RX_DP<12>: length 173.7
  IN2 w0.089: v3(68.85,79.97) 69.42,80.37 70.85,80.37 71.27,80.44 72.2,81.09 72.95,81.09 73.48,80.72 74.38,80.72 74.43,80.77 74.45,80.77
  IN2 w0.145: 74.45,80.77 75.28,80.77 84.4,82.38 88.01,81.74 92.57,82.54 97.09,81.75 100.94,82.43 103.03,83.89 144.65,91.23 171.67,86.47 194.43,90.48 205.94,88.45 211.17,89.37 224.12,87.09 224.95,86.51 225.76,85.36 226.24,82.63 225.96,81.04 225.96,80 226.96,78.99 226.96,75.19 226.7,74.93 226.52,74.84 226.46,74.64 J3.A68
  BOTTOM w0.135: U1.E17 v3(68.85,79.97)
PE_SLOT3_RX_DP<13>: length 173.7
  IN2 w0.089: 73.02,79.79 72.99,79.79 72.95,79.74 69.96,79.74 69.78,79.57 69.42,79.57 v3(68.85,79.17)
  IN2 w0.145: J3.A72 222.46,74.64 222.52,74.84 222.7,74.93 222.96,75.19 222.96,78.99 221.97,79.99 221.97,82.39 221.43,85.47 221.03,86.03 220.17,86.64 210.52,88.34 205.36,87.43 194.13,89.41 172.02,85.51 144.76,90.31 128.46,87.44 112.1,84.55 111.81,84.14 111.91,83.58 111.79,83.41 111.43,83.35 111.27,83.46 111.17,84.03 110.76,84.32 110.26,84.23 109.97,83.82 110.07,83.26 109.95,83.09 109.6,83.02 109.43,83.14 109.33,83.7 108.92,83.99 108.42,83.91 108.14,83.49 108.25,82.86 108.13,82.7 107.77,82.63 107.6,82.75 107.49,83.38 107.08,83.67 103.29,83 101.11,81.47 97.02,80.75 92.82,81.49 88.08,80.66 84.79,81.24 75.39,79.58 74.45,79.75 74.22,79.79 73.02,79.79
  BOTTOM w0.135: U1.E16 v3(68.85,79.17)
PE_SLOT3_RX_DP<14>: length 161.5
  IN2 w0.089: v3(68.85,77.57) 69.42,77.97 70.46,77.97 70.84,78.03 71.68,78.62 72.35,78.79 72.54,78.75 72.72,78.72 72.85,78.7 72.91,78.73 72.93,78.73
  IN2 w0.145: J3.A76 218.46,74.64 218.52,74.84 218.7,74.93 218.96,75.19 218.96,78.99 217.98,79.97 217.98,80.54 217.82,81.45 217.38,82.09 216.13,82.96 215.05,83.41 212.91,84.91 193.96,88.25 172.36,84.44 148.87,88.58 96.94,79.42 92.3,80.24 88.03,79.49 84.52,80.11 75.31,78.48 74.45,78.57 72.93,78.73
  BOTTOM w0.135: U1.E14 v3(68.85,77.57)
PE_SLOT3_RX_DP<15>: length 160.7
  IN2 w0.089: 73.46,77.39 73.44,77.39 73.4,77.34 69.96,77.34 69.78,77.17 69.42,77.17 v3(68.85,76.77)
  IN2 w0.145: 73.46,77.39 73.93,77.39 73.94,77.39 74.45,77.35 75.49,77.26 84.38,78.83 87.88,78.21 92.1,78.96 96.22,78.23 100.52,78.99 101.23,78.5 101.33,77.95 101.49,77.83 101.85,77.89 101.97,78.06 101.87,78.61 102.16,79.02 102.66,79.11 103.07,78.82 103.16,78.3 103.33,78.18 103.68,78.25 103.8,78.41 103.71,78.93 104,79.34 148.69,87.22 172.27,83.07 175.18,83.58 194.73,87.03 212.09,83.97 212.99,83.33 213.81,82.17 213.95,81.38 213.95,80.01 214.96,78.99 214.96,75.19 214.7,74.93 214.52,74.84 214.46,74.64 J3.A80
  BOTTOM w0.135: U1.E13 v3(68.85,76.77)
PE_SLOT3_TX_C_DN<0>: length 243.5
  BOTTOM w0.089: 57.81,85.44 57.81,85.42 57.75,85.36 57.75,84.61 58,84.37 U1.V23
  BOTTOM w0.135: C43.1 279.68,85.46 279.68,85.83 278.64,87.32 277.69,87.98 277.49,87.94 277.06,88.24 277.02,88.45 276.58,88.75 276.39,88.72 275.95,89.03 275.92,89.22 275.48,89.53 275.29,89.5 274.85,89.8 274.81,89.99 274.37,90.3 274.18,90.27 273.74,90.58 273.71,90.77 273.27,91.08 273.08,91.04 272.64,91.35 272.6,91.54 272.16,91.85 271.97,91.82 271.53,92.13 271.5,92.32 264.62,97.13 249.04,99.88 246.56,101.61 216.77,106.86 202.91,104.42 196.3,105.59 181.01,102.89 v6(141.59,109.84) 139.8,110.15 128.09,112.22 127.74,112.22 100.38,107.34 100.37,107.34 74.48,102.72 74.33,102.69 74.21,102.51 73.78,102.44 73.61,102.56 73.17,102.48 73.05,102.31 72.62,102.23 72.45,102.35 72.01,102.28 71.89,102.1 71.46,102.03 71.28,102.15 70.85,102.07 70.73,101.9 70.26,101.82 70.09,101.94 68.42,101.64 61.57,94.79 61.57,94.59 61.2,94.22 61,94.22 60.69,93.91 60.69,93.71 60.33,93.35 60.12,93.35 59.81,93.04 59.81,92.86 59.43,92.47 59.25,92.47 58.94,92.16 58.94,91.96 58.57,91.59 58.37,91.59 57.53,90.75 57.53,89.23 57.66,89.1 57.66,88.51 57.53,88.38 57.53,87.84 57.66,87.72 57.66,87.13 57.53,87 57.53,86.54 57.81,86.26 57.81,85.44
PE_SLOT3_TX_C_DN<1>: length 241.5
  BOTTOM w0.089: 58.72,86.23 58.72,86.21 58.66,86.15 58.66,84.48 58.78,84.37 U1.U23
  BOTTOM w0.135: C44.1 275.64,85.46 275.64,86.81 275.19,87.47 274.28,88.1 274.13,88.07 273.62,88.43 273.59,88.58 272.5,89.34 272.24,89.3 271.96,88.89 271.45,88.8 271.02,89.1 270.93,89.61 271.21,90.02 271.17,90.28 270.95,90.43 270.69,90.38 270.41,89.98 269.9,89.89 269.47,90.19 269.38,90.7 269.66,91.1 269.62,91.36 269.4,91.52 269.13,91.47 268.85,91.07 268.34,90.98 267.92,91.28 267.83,91.79 268.11,92.19 268.04,92.6 262.91,96.19 260.15,96.61 255.74,97.39 255.59,97.28 255.01,97.38 254.9,97.54 254.37,97.63 254.22,97.52 253.63,97.63 253.53,97.78 253,97.87 252.85,97.77 252.26,97.87 252.16,98.02 251.63,98.11 251.5,98.03 250.87,98.14 250.78,98.26 250.25,98.36 250.11,98.26 249.51,98.36 249.41,98.51 247.9,98.77 245.38,100.54 217.06,105.53 202.75,103.01 196.44,104.12 180.94,101.39 v6(138.49,108.88) 136.89,109.16 127.87,110.75 99,105.66 99,105.66 77.17,101.81 77.05,101.65 76.52,101.56 76.36,101.67 75.83,101.58 75.71,101.41 75.18,101.32 75.02,101.43 74.49,101.34 74.38,101.18 73.85,101.08 73.69,101.2 73.15,101.1 73.04,100.94 72.51,100.85 72.35,100.96 71.82,100.87 71.7,100.71 71.17,100.61 71.01,100.73 69.99,100.55 67.62,98.88 64.13,95.4 64.13,95.3 64.13,95.2 63.75,94.81 63.65,94.81 63.55,94.81 63.17,94.43 63.17,94.33 63.17,94.23 62.79,93.85 62.69,93.85 62.58,93.85 62.2,93.47 62.2,93.37 62.2,93.27 61.82,92.89 61.72,92.89 61.62,92.89 61.24,92.51 61.24,92.4 61.24,92.3 60.86,91.92 60.76,91.92 60.66,91.92 60.28,91.54 60.28,91.44 60.28,91.34 59.89,90.96 59.79,90.96 59.69,90.96 59.01,90.27 59.01,86.82 58.72,86.53 58.72,86.23
